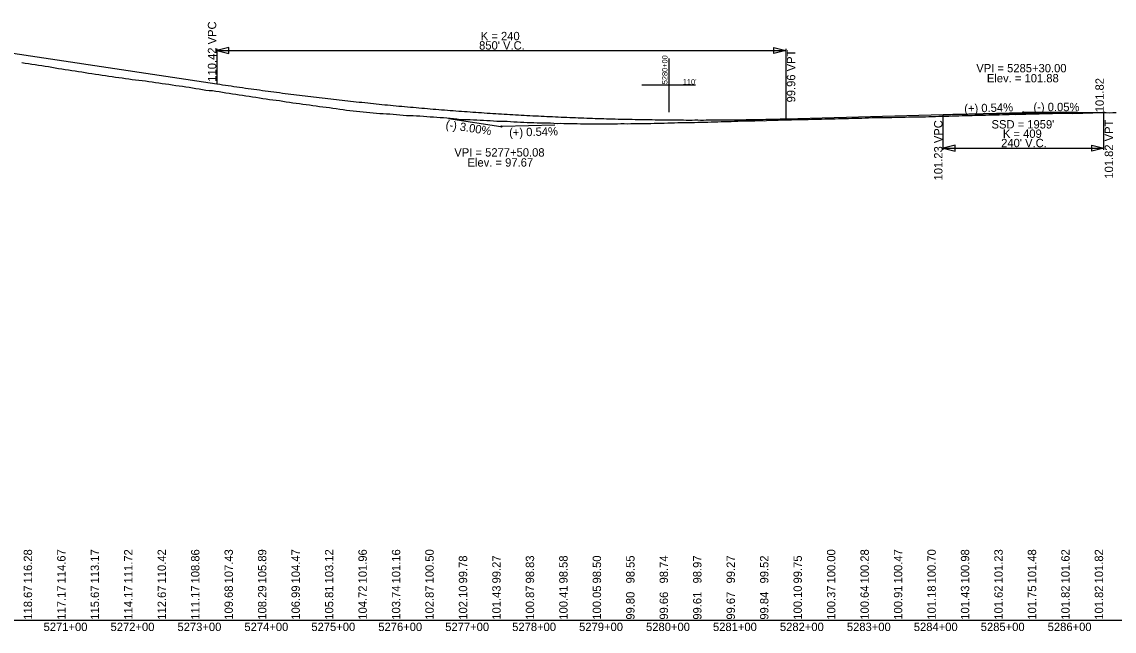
# Model space of a CAD drawing. Extents: x 2147288 to 2220488, y 740833 to 759333.
# Drawn here: x 2159415 to 2161047, y 758067 to 758978 of the extents above; entities that cross this region are included whole.
import ezdxf

# ---------------------------------------------------------------- set-up
doc = ezdxf.new("R2010")
doc.units = 0
for name, color, linetype in [('RD_DDB_GradeTX', 7, 'Continuous'), ('RD_DDB_Profile_EX', 7, 'Continuous'), ('RD_DDB_Profile_Lbl', 7, 'Continuous'), ('RD_DDB_Profile_PR', 7, 'Continuous'), ('RD_DDB_StaTX', 7, 'Continuous'), ('RD_DDB_StripGrade', 7, 'Continuous'), ('RD_DDB_VCLbl', 7, 'Continuous'), ('RD_GPK_Profile_Cell', 7, 'Continuous')]:
    doc.layers.add(name, color=color, linetype=linetype)

msp = doc.modelspace()

# ---------------------------------------------------------------- linework, layer by layer
at = {"layer": 'RD_DDB_GradeTX'}
for p, q in [((2160831.1, 758840.7), (2160910.1, 758842.8)), ((2160991.1, 758842.6), (2160912.1, 758842.8)), ((2160052, 758833.6), (2160130.2, 758821.9)), ((2160211.1, 758823.9), (2160132.2, 758821.8))]:
    msp.add_line(p, q, dxfattribs=at)
for centre in [(2160911.1, 758842.8), (2161031.1, 758842.5), (2160131.2, 758821.8)]:
    msp.add_circle(centre, 1, dxfattribs=at)
at = {"layer": 'RD_DDB_Profile_EX'}
for points in [[(2159414.6, 758917.4), (2159419.6, 758916.6), (2159424.6, 758915.9), (2159429.6, 758915.1), (2159434.6, 758914.3), (2159439.6, 758913.5), (2159444.6, 758912.8), (2159449.6, 758911.9), (2159454.6, 758911.4), (2159459.6, 758910.6), (2159464.6, 758909.5), (2159469.6, 758908.7), (2159474.6, 758907.8), (2159479.6, 758907), (2159484.6, 758906.3), (2159489.6, 758905.5), (2159494.6, 758904.8), (2159499.6, 758904.1), (2159504.6, 758903.4), (2159509.6, 758902.4), (2159514.6, 758901.7), (2159519.6, 758900.9), (2159524.6, 758900.2), (2159529.6, 758899.5), (2159534.6, 758898.7)], [(2159534.6, 758898.7), (2159539.6, 758897.9), (2159544.6, 758897.2), (2159549.6, 758896.5), (2159554.6, 758895.8), (2159559.6, 758895.2), (2159564.6, 758894.4), (2159569.6, 758893.7), (2159574.6, 758893), (2159579.6, 758892.2), (2159584.6, 758891.6), (2159589.6, 758891.2), (2159594.6, 758890.6), (2159599.6, 758890), (2159604.6, 758889.3), (2159609.6, 758888.6), (2159614.6, 758887.8), (2159619.6, 758886.9), (2159624.6, 758886.2), (2159629.6, 758885.8), (2159634.6, 758885), (2159639.6, 758884.1), (2159644.6, 758883.3), (2159649.6, 758882.5), (2159654.6, 758881.9), (2159659.6, 758881.2), (2159664.6, 758880.4), (2159669.6, 758879.5), (2159674.6, 758878.8), (2159679.6, 758878), (2159684.6, 758877), (2159689.6, 758876.1), (2159694.6, 758875.8), (2159699.6, 758875.4), (2159704.6, 758874.7), (2159709.6, 758873.9), (2159714.6, 758872.9), (2159719.6, 758872.3), (2159724.6, 758871.6), (2159729.6, 758870.8), (2159734.6, 758870.1), (2159739.6, 758869.3), (2159744.6, 758868.5), (2159749.6, 758867.7), (2159754.6, 758866.9), (2159759.6, 758866.2), (2159764.6, 758865.4), (2159769.6, 758864.7), (2159774.6, 758863.9), (2159779.6, 758863.1), (2159784.6, 758862.3), (2159789.6, 758861.7), (2159794.6, 758861.1), (2159799.6, 758860.5), (2159804.6, 758859.6), (2159809.6, 758858.7), (2159814.6, 758858), (2159819.6, 758857.3), (2159824.6, 758856.8), (2159829.6, 758856), (2159834.6, 758855.3), (2159839.6, 758854.9), (2159844.6, 758854.2), (2159849.6, 758853.4), (2159854.6, 758852.7), (2159859.6, 758851.9), (2159864.6, 758851.3), (2159869.6, 758850.8), (2159874.6, 758850), (2159879.6, 758849.3), (2159884.6, 758848.5), (2159889.6, 758847.8), (2159894.6, 758847.1), (2159899.6, 758846.3), (2159904.6, 758845.6), (2159909.6, 758845.2), (2159914.6, 758844.8), (2159919.6, 758844.4), (2159924.6, 758843.9), (2159929.6, 758843.4), (2159934.6, 758842.8), (2159939.6, 758842.3), (2159944.6, 758841.8), (2159949.6, 758841.3), (2159954.6, 758841.2), (2159959.6, 758840.9), (2159964.6, 758840.5), (2159969.6, 758840.4), (2159974.6, 758839.9), (2159979.6, 758839.4), (2159984.6, 758838.8), (2159989.6, 758838.4), (2159994.6, 758838.4), (2159999.6, 758838.2), (2160004.6, 758837.9), (2160009.6, 758837.5), (2160014.6, 758837.1), (2160019.6, 758836.6), (2160024.6, 758836.2), (2160029.6, 758836), (2160034.6, 758835.8)], [(2160034.6, 758835.8), (2160039.6, 758835.4), (2160044.6, 758835), (2160049.6, 758834.7), (2160054.6, 758834.2), (2160059.6, 758833.8), (2160064.6, 758833.1), (2160069.6, 758832.4), (2160074.6, 758832.4), (2160079.6, 758832.4), (2160084.6, 758832.1), (2160089.6, 758831.9), (2160094.6, 758831.6), (2160099.6, 758831.3), (2160104.6, 758831.1), (2160109.6, 758830.9), (2160114.6, 758830.7), (2160119.6, 758830.3), (2160124.6, 758830), (2160129.6, 758829.8), (2160134.6, 758829.7), (2160139.6, 758829.6), (2160144.6, 758829.4), (2160149.6, 758829), (2160154.6, 758828.6), (2160159.6, 758828.4), (2160164.6, 758828.2), (2160169.6, 758828), (2160174.6, 758827.8), (2160179.6, 758827.6), (2160184.6, 758827.5), (2160189.6, 758827.5), (2160194.6, 758827.4), (2160199.6, 758827.3), (2160204.6, 758827.1), (2160209.6, 758826.6), (2160214.6, 758826.3), (2160219.6, 758826.6), (2160224.6, 758826.4), (2160229.6, 758826.3), (2160234.6, 758826.4), (2160239.6, 758826.4), (2160244.6, 758826.2), (2160249.6, 758826), (2160254.6, 758825.9), (2160259.6, 758826), (2160264.6, 758825.9), (2160269.6, 758825.9), (2160274.6, 758826), (2160279.6, 758826), (2160284.6, 758826), (2160289.6, 758825.9), (2160294.6, 758825.9), (2160299.6, 758825.7), (2160304.6, 758826), (2160309.6, 758826.1), (2160314.6, 758826.1), (2160319.6, 758826), (2160324.6, 758826.1), (2160329.6, 758826.1), (2160334.6, 758826.2), (2160339.6, 758826.2), (2160344.6, 758826.3), (2160349.6, 758826.4), (2160354.6, 758826.5), (2160359.6, 758826.8), (2160364.6, 758827), (2160369.6, 758827), (2160374.6, 758827), (2160379.6, 758827.1), (2160384.6, 758827.2), (2160389.6, 758827.5), (2160394.6, 758827.6), (2160399.6, 758827.7), (2160404.6, 758827.8), (2160409.6, 758827.9), (2160414.6, 758828), (2160419.6, 758828), (2160424.6, 758828.1), (2160429.6, 758828.2), (2160434.6, 758828.3), (2160439.6, 758828.5), (2160444.6, 758828.6), (2160449.6, 758828.8), (2160454.6, 758828.9), (2160459.6, 758829.1), (2160464.6, 758829.1), (2160469.6, 758829.5), (2160474.6, 758829.4), (2160479.6, 758829.7), (2160484.6, 758829.9), (2160489.6, 758830.1), (2160494.6, 758830.2), (2160499.6, 758830.2), (2160504.6, 758830.3), (2160509.6, 758830.5), (2160514.6, 758830.6), (2160519.6, 758830.6), (2160524.6, 758830.5), (2160529.6, 758831), (2160534.6, 758831.1)], [(2160534.6, 758831.1), (2160539.6, 758831.2), (2160544.6, 758831.3), (2160549.6, 758831.5), (2160554.6, 758831.6), (2160559.6, 758831.8), (2160564.6, 758831.9), (2160569.6, 758832), (2160574.6, 758832), (2160579.6, 758832.2), (2160584.6, 758832.3), (2160589.6, 758832.4), (2160594.6, 758832.6), (2160599.6, 758832.7), (2160604.6, 758832.8), (2160609.6, 758832.9), (2160614.6, 758833.1), (2160619.6, 758833.2), (2160624.6, 758833.3), (2160629.6, 758833.4), (2160634.6, 758833.5), (2160639.6, 758833.6), (2160644.6, 758833.8), (2160649.6, 758833.9), (2160654.6, 758834), (2160659.6, 758834.1), (2160664.6, 758834.3), (2160669.6, 758834.4), (2160674.6, 758834.5), (2160679.6, 758834.8), (2160684.6, 758835), (2160689.6, 758835), (2160694.6, 758835.1), (2160699.6, 758835.2), (2160704.6, 758835.1), (2160709.6, 758835.3), (2160714.6, 758835.3), (2160719.6, 758835.5), (2160724.6, 758835.7), (2160729.6, 758835.7), (2160734.6, 758835.9), (2160739.6, 758836), (2160744.6, 758836), (2160749.6, 758836.1), (2160754.6, 758836.2), (2160759.6, 758836.3), (2160764.6, 758836.4), (2160769.6, 758836.6), (2160774.6, 758836.7), (2160779.6, 758836.8), (2160784.6, 758837.1), (2160789.6, 758837.2), (2160794.6, 758837.3), (2160799.6, 758837.4), (2160804.6, 758837.6), (2160809.6, 758837.7), (2160814.6, 758837.9), (2160819.6, 758838), (2160824.6, 758838.2), (2160829.6, 758838.3), (2160834.6, 758838.4), (2160839.6, 758838.5), (2160844.6, 758838.6), (2160849.6, 758838.7), (2160854.6, 758838.8), (2160859.6, 758839), (2160864.6, 758839.1), (2160869.6, 758839.2), (2160874.6, 758839.3), (2160879.6, 758839.5), (2160884.6, 758839.7), (2160889.6, 758839.9), (2160894.6, 758840), (2160899.6, 758839.9), (2160904.6, 758840), (2160909.6, 758840.4), (2160914.6, 758840.2), (2160919.6, 758840.6), (2160924.6, 758840.7), (2160929.6, 758840.8), (2160934.6, 758840.9), (2160939.6, 758841), (2160944.6, 758841), (2160949.6, 758841.1), (2160954.6, 758841.2), (2160959.6, 758841.6), (2160964.6, 758841.7), (2160969.6, 758841.7), (2160974.6, 758841.8), (2160979.6, 758841.6), (2160984.6, 758841.4), (2160989.6, 758841.6), (2160994.6, 758841.7), (2160999.6, 758841.9), (2161004.6, 758842.2), (2161009.6, 758842.3), (2161014.6, 758842.4), (2161019.6, 758842.5), (2161024.6, 758842.5), (2161029.6, 758842.5), (2161034.6, 758842.6)], [(2161034.6, 758842.6), (2161039.6, 758842.4), (2161044.6, 758842.5), (2161049.6, 758842.5)]]:
    msp.add_lwpolyline(points, dxfattribs=at)
at = {"layer": 'RD_DDB_Profile_PR'}
for p, q in [((2159381.1, 758934.3), (2159706.2, 758885.5)), ((2160556.2, 758833.2), (2160791.1, 758839.6))]:
    msp.add_line(p, q, dxfattribs=at)
for points in [[(2159706.2, 758885.5), (2159723.2, 758883), (2159740.2, 758880.5), (2159757.2, 758878.1), (2159774.2, 758875.8), (2159791.2, 758873.5), (2159808.2, 758871.3), (2159825.2, 758869.1), (2159842.2, 758867), (2159859.2, 758865), (2159876.2, 758863), (2159893.2, 758861.1), (2159910.2, 758859.2), (2159927.2, 758857.5), (2159944.2, 758855.7), (2159961.2, 758854), (2159978.2, 758852.4), (2159995.2, 758850.9), (2160012.2, 758849.4), (2160029.2, 758847.9), (2160046.2, 758846.6), (2160063.2, 758845.2), (2160080.2, 758844), (2160097.2, 758842.8), (2160114.2, 758841.6), (2160131.2, 758840.6), (2160148.2, 758839.6), (2160165.2, 758838.6), (2160182.2, 758837.7), (2160199.2, 758836.9), (2160216.2, 758836.1), (2160233.2, 758835.4), (2160250.2, 758834.7), (2160267.2, 758834.1), (2160284.2, 758833.6), (2160301.2, 758833.1), (2160318.2, 758832.7), (2160335.2, 758832.4), (2160352.2, 758832.1), (2160369.2, 758831.8), (2160386.2, 758831.7), (2160403.2, 758831.5), (2160420.2, 758831.5), (2160437.2, 758831.5), (2160454.2, 758831.6), (2160471.2, 758831.7), (2160488.2, 758831.9), (2160505.2, 758832.1), (2160522.2, 758832.4), (2160539.2, 758832.8), (2160556.2, 758833.2)], [(2160791.1, 758839.6), (2160795.9, 758839.7), (2160800.7, 758839.8), (2160805.5, 758840), (2160810.3, 758840.1), (2160815.1, 758840.2), (2160819.9, 758840.3), (2160824.7, 758840.4), (2160829.5, 758840.5), (2160834.3, 758840.6), (2160839.1, 758840.7), (2160843.9, 758840.8), (2160848.7, 758840.9), (2160853.5, 758841), (2160858.3, 758841.1), (2160863.1, 758841.2), (2160867.9, 758841.3), (2160872.7, 758841.4), (2160877.5, 758841.5), (2160882.3, 758841.5), (2160887.1, 758841.6), (2160891.9, 758841.7), (2160896.7, 758841.8), (2160901.5, 758841.8), (2160906.3, 758841.9), (2160911.1, 758841.9), (2160915.9, 758842), (2160920.7, 758842.1), (2160925.5, 758842.1), (2160930.3, 758842.2), (2160935.1, 758842.2), (2160939.9, 758842.2), (2160944.7, 758842.3), (2160949.5, 758842.3), (2160954.3, 758842.4), (2160959.1, 758842.4), (2160963.9, 758842.4), (2160968.7, 758842.5), (2160973.5, 758842.5), (2160978.3, 758842.5), (2160983.1, 758842.5), (2160987.9, 758842.5), (2160992.7, 758842.5), (2160997.5, 758842.6), (2161002.3, 758842.6), (2161007.1, 758842.6), (2161011.9, 758842.6), (2161016.7, 758842.6), (2161021.5, 758842.6), (2161026.3, 758842.6), (2161031.1, 758842.5)]]:
    msp.add_spline(points, degree=3, dxfattribs=at)
at = {"layer": 'RD_DDB_VCLbl'}
for p, q in [((2159706.2, 758938), (2159706.2, 758885.5)), ((2159706.2, 758935.5), (2160556.2, 758935.5)), ((2160556.2, 758938), (2160556.2, 758833.2)), ((2160791.1, 758787.1), (2160791.1, 758839.6)), ((2161031.1, 758787.1), (2161031.1, 758842.5)), ((2160791.1, 758789.6), (2161031.1, 758789.6))]:
    msp.add_line(p, q, dxfattribs=at)
for points in [[(2159724.2, 758940), (2159706.2, 758935.5), (2159724.2, 758931)], [(2160538.2, 758940), (2160556.2, 758935.5), (2160538.2, 758931)], [(2160809.1, 758794.1), (2160791.1, 758789.6), (2160809.1, 758785.1)], [(2161013.1, 758794.1), (2161031.1, 758789.6), (2161013.1, 758785.1)]]:
    msp.add_lwpolyline(points, close=True, dxfattribs=at)
at = {"layer": 'RD_GPK_Profile_Cell'}
for p, q in [((2160381.1, 758923.4), (2160381.1, 758843.4)), ((2160421.1, 758883.4), (2160341.1, 758883.4)), ((2148888.3, 758083.4), (2165888.3, 758083.4))]:
    msp.add_line(p, q, dxfattribs=at)

# ---------------------------------------------------------------- texts
at = {"layer": 'RD_DDB_GradeTX'}
for s, rotation, p in [('(+) 0.54%', 1.5466, (2160822.8, 758842.4)), ('(-) 0.05%', 359.8661, (2160926, 758844.8)), ('(-) 3.00%', 351.4692, (2160047.3, 758818.9)), ('(+) 0.54%', 1.5466, (2160142.9, 758806.6))]:
    msp.add_text(s, height=12.5, rotation=rotation, dxfattribs=at).set_placement(p)
at = {"layer": 'RD_DDB_Profile_Lbl'}
for s, p in [('VPI = 5285+30.00', (2160840.7, 758902.8)), ('Elev. = 101.88', (2160856.5, 758887.8)), ('VPI = 5277+50.08', (2160060.9, 758776.8)), ('Elev. = 97.67', (2160080.6, 758761.8))]:
    msp.add_text(s, height=12.5, dxfattribs=at).set_placement(p)
msp.add_text('101.82', height=12.5, rotation=90, dxfattribs=at).set_placement((2161031.1, 758843.1))
at = {"layer": 'RD_DDB_StaTX'}
for s, p in [('5271+00', (2159447.3, 758067.2)), ('5272+00', (2159547.3, 758067.2)), ('5273+00', (2159647.3, 758067.2)), ('5274+00', (2159747.3, 758067.2)), ('5275+00', (2159847.3, 758067.2)), ('5276+00', (2159947.3, 758067.2)), ('5277+00', (2160047.3, 758067.2)), ('5278+00', (2160147.3, 758067.2)), ('5279+00', (2160247.3, 758067.2)), ('5280+00', (2160347.3, 758067.2)), ('5281+00', (2160447.3, 758067.2)), ('5282+00', (2160547.3, 758067.2)), ('5283+00', (2160647.3, 758067.2)), ('5284+00', (2160747.3, 758067.2)), ('5285+00', (2160847.3, 758067.2)), ('5286+00', (2160947.3, 758067.2))]:
    msp.add_text(s, height=12.5, dxfattribs=at).set_placement(p)
at = {"layer": 'RD_DDB_StripGrade'}
for s, p in [('110.42 VPC', (2159705.2, 758888.8)), ('99.96 VPT', (2160570.2, 758857.8)), ('101.23 VPC', (2160790.1, 758741.1)), ('101.82 VPT', (2161045, 758743.8)), ('116.28', (2159430.1, 758138.4)), ('114.67', (2159480.1, 758138.4)), ('113.17', (2159530.1, 758138.4)), ('111.72', (2159580.1, 758138.4)), ('110.42', (2159630.1, 758138.4)), ('108.86', (2159680.1, 758138.4)), ('107.43', (2159730.1, 758138.4)), ('105.89', (2159780.1, 758138.4)), ('104.47', (2159830.1, 758138.4)), ('103.12', (2159880.1, 758138.4)), ('101.96', (2159930.1, 758138.4)), ('101.16', (2159980.1, 758138.4)), ('100.50', (2160030.1, 758138.4)), ('100.00', (2160630.1, 758138.4)), ('100.28', (2160680.1, 758138.4)), ('100.47', (2160730.1, 758138.4)), ('100.70', (2160780.1, 758138.4)), ('100.98', (2160830.1, 758138.4)), ('101.23', (2160880.1, 758138.4)), ('101.48', (2160930.1, 758138.4)), ('101.62', (2160980.1, 758138.4)), ('101.82', (2161030.1, 758138.4)), ('99.78', (2160080.1, 758138.4)), ('99.27', (2160130.1, 758138.4)), ('98.83', (2160180.1, 758138.4)), ('98.58', (2160230.1, 758138.4)), ('98.50', (2160280.1, 758138.4)), ('98.55', (2160330.1, 758138.4)), ('98.74', (2160380.1, 758138.4)), ('98.97', (2160430.1, 758138.4)), ('99.27', (2160480.1, 758138.4)), ('99.52', (2160530.1, 758138.4)), ('99.75', (2160580.1, 758138.4)), ('118.67', (2159430.1, 758084.2)), ('117.17', (2159480.1, 758084.2)), ('115.67', (2159530.1, 758084.2)), ('114.17', (2159580.1, 758084.2)), ('112.67', (2159630.1, 758084.2)), ('111.17', (2159680.1, 758084.2)), ('109.68', (2159730.1, 758084.2)), ('108.29', (2159780.1, 758084.2)), ('106.99', (2159830.1, 758084.2)), ('105.81', (2159880.1, 758084.2)), ('104.72', (2159930.1, 758084.2)), ('103.74', (2159980.1, 758084.2)), ('102.87', (2160030.1, 758084.2)), ('102.10', (2160080.1, 758084.2)), ('101.43', (2160130.1, 758084.2)), ('100.87', (2160180.1, 758084.2)), ('100.41', (2160230.1, 758084.2)), ('100.05', (2160280.1, 758084.2)), ('100.10', (2160580.1, 758084.2)), ('100.37', (2160630.1, 758084.2)), ('100.64', (2160680.1, 758084.2)), ('100.91', (2160730.1, 758084.2)), ('101.18', (2160780.1, 758084.2)), ('101.43', (2160830.1, 758084.2)), ('101.62', (2160880.1, 758084.2)), ('101.75', (2160930.1, 758084.2)), ('101.82', (2160980.1, 758084.2)), ('101.82', (2161030.1, 758084.2)), ('99.80', (2160330.1, 758084.2)), ('99.66', (2160380.1, 758084.2)), ('99.61', (2160430.1, 758084.2)), ('99.67', (2160480.1, 758084.2)), ('99.84', (2160530.1, 758084.2))]:
    msp.add_text(s, height=12.5, rotation=90, dxfattribs=at).set_placement(p)
at = {"layer": 'RD_DDB_VCLbl'}
for s, p in [("850' V.C.", (2160097.9, 758936.8)), ('K = 240', (2160100.4, 758950.8)), ("SSD = 1959'", (2160863.4, 758818.8)), ("240' V.C.", (2160877.8, 758790.8)), ('K = 409', (2160880.4, 758804.8))]:
    msp.add_text(s, height=12.5, dxfattribs=at).set_placement(p)
at = {"layer": 'RD_GPK_Profile_Cell'}
msp.add_text('5280+00', height=8, rotation=90, dxfattribs=at).set_placement((2160379.3, 758885))
msp.add_text("110'", height=8, dxfattribs=at).set_placement((2160402.2, 758884.6))

doc.saveas('drawing.dxf')
